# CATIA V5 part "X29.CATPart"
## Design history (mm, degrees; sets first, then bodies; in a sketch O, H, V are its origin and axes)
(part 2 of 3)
  St3DCurveFeature52 "CATSt3DCurveFeatureName": Order 6, CreationType 2, ClosureMode false, ConstructionPoints ({point type OnCurve, Support Join20, Real 0}; {point type OnCurve, Support St3DCurveFeature4, Real 0.751354}), SymmetryMode false
  Join21 "JOINJOINFRUIT": Elements (Join20; St3DCurveFeature52)
  Loft14 "OHTHEFRUIT": Sections (Join21; St3DCurveFeature50), Guides (St3DCurveFeature4; St3DCurveFeature51)
  Symmetry9: ToTransfor Loft14, Reference zx-plane
  Fill3: Boundary (St3DCurveFeature37; St3DCurveFeature36)
  Fill4: Boundary (edge of MultiSel6; edge of MultiSel6)
  Line9: type PtPt, FirstPoint vertex of St3DCurveFeature29, SecondPoint vertex of St3DCurveFeature31
  Point13: type OnCurve, Support Line9, Ratio 0.5
  Plane5: type OffsetPt, RefPlane xy-plane, RefPoint Point13
  Sketch12 on Plane5, origin (0, 0, 60.9519), H (1, 0, 0), V (0, 1, 0)
    line L1 (-1313.864, 33.3458) -> (-1313.864, 0)
    point P1 (-1313.864, 0)
    line L2 (-1313.864, 0) -> (-1285.9, 0)
    point P2 (-1285.9, 0)
    coincidence: P1 H
    vertical: L1 V
    horizontal: L2 H
  Line10: type PtPt, FirstPoint vertex [element of Sketch12 | element of Sketch12], SecondPoint vertex of St3DCurveFeature29
  Circle8: type 2PointsRad, Start 0, End 180, FirstPoint vertex of St3DCurveFeature29, SecondPoint vertex of St3DCurveFeature31, Support Sketch12.L2, Radius 62.383
  Plane6: type 3Points, Element1 vertex [element of Sketch12 | element of Sketch12], Element2 vertex of St3DCurveFeature29, Element3 vertex of St3DCurveFeature31
  Sketch13 on Plane6, origin (-1313.864, 0, 0), H (0, -1, 0), V (0, 0, 1)
    projected point E1 (0, 60.9519) from vertex [element of Sketch12 | element of Sketch12]
    arc A1 centre (0, 60.9519) radius 62.3831 from (-33.3458, 113.6748) to (-33.3458, 8.2289) ccw
  Loft15 "IMPROVED TURBINE INTAKE": Sections (St3DCurveFeature32; St3DCurveFeature34; Sketch13.A1), Guides (St3DCurveFeature29; St3DCurveFeature31)
  Symmetry10: ToTransfor Loft15, Reference zx-plane
  Sketch14 on Plane6, origin (-1313.864, 0, 0), H (0, -1, 0), V (0, 0, 1)
    projected point E1 (0, 60.9519) from vertex of Sketch13.E1
    projected point E2 (-33.3458, 113.6748) from vertex of St3DCurveFeature29
  Sketch15 on Plane5, origin (0, 0, 60.9519), H (1, 0, 0), V (0, 1, 0)
    projected line E1 (-1416.7, -3.85) -> (-1396.2, -3.85) from Sketch7.L16
    projected line E2 (-1396.2, -3.85) -> (-1396.2, 40.7) from Sketch7.L15
  Circle9: type CenterAxis, Start 0, End 180, Pt vertex of Sketch14.E2, Axis {line type PtPt, FirstPoint vertex of Sketch14.E1, SecondPoint Sketch12.P2}, Radius 62.383
  Point14: type OnPlane, Support zx-plane, RefPoint {extract ExtractElem vertex of St3DCurveFeature53}, H 0, V 0, Direction (-1, 0, 0)
  St3DCurveFeature53 "CATSt3DCurveFeatureName": Order 6, CreationType 2, ClosureMode false, ConstructionPoints ({point type OnCurve, Support Join18, Real 0.5}; {point type Coord, X -1064.6398, Y 0, Z 114.1394}; {point type Coord, X -1120.2775, Y 0, Z 116.1082}; {point type Coord, X -1193.3538, Y 0, Z 118.8994}; {point type Coord, X -1262.5354, Y 0, Z 123.2155}; {point type Coord, X 0, Y 0, Z 0, RefPoint {intersect ToIntersect1 zx-plane, ToIntersect2 Circle9}}), SymmetryMode false
  St3DCurveFeature54 "CATSt3DCurveFeatureName": Order 6, CreationType 2, ClosureMode false, ConstructionPoints ({point type OnCurve, Support St3DCurveFeature53, Real 0.219235}; {point type Coord, X -1060.5942, Y 8.1231, Z 113.32}; {point type Coord, X -1060.5905, Y 21.1239, Z 110.6941}; {point type OnCurve, Support St3DCurveFeature29, Real 0.688548}), SymmetryMode false
  St3DCurveFeature55 "CATSt3DCurveFeatureName": Order 6, CreationType 2, ClosureMode false, ConstructionPoints ({point type OnCurve, Support St3DCurveFeature53, Real 0.494443}; {point type Coord, X -1149.914, Y 5.9376, Z 116.5421}; {point type Coord, X -1149.8784, Y 21.8631, Z 111.8728}; {point type OnCurve, Support St3DCurveFeature29, Real 0.798273}), SymmetryMode false
  St3DCurveFeature56 "CATSt3DCurveFeatureName": Order 6, CreationType 2, ClosureMode false, ConstructionPoints ({point type OnCurve, Support St3DCurveFeature53, Real 0.810661}; {point type Coord, X -1252.4315, Y 8.3831, Z 122.1937}; {point type Coord, X -1252.4439, Y 20.5266, Z 119.6729}; {point type OnCurve, Support St3DCurveFeature29, Real 0.92444}), SymmetryMode false
  St3DCurveFeature57 "CATSt3DCurveFeatureName": Order 6, CreationType 2, ClosureMode false, ConstructionPoints ({point type OnCurve, Support St3DCurveFeature53, Real 0.933465}; {point type Coord, X -1292.2767, Y 7.7806, Z 123.3227}; {point type Coord, X -1292.2891, Y 21.9459, Z 120.0376}; {point type OnCurve, Support St3DCurveFeature29, Real 0.973447}), SymmetryMode false
  Circle10: type 2PointsRad, Start 0, End 180, FirstPoint Point14, SecondPoint vertex of Sketch14.E2, Support Plane6, Radius 62.383
  Join22: Elements (St3DCurveFeature41; St3DCurveFeature50)
  Loft16: Sections (Join22; St3DCurveFeature54; St3DCurveFeature55; St3DCurveFeature56; Circle10), Guides (St3DCurveFeature53; St3DCurveFeature29)
  Symmetry11: ToTransfor Loft16, Reference zx-plane
  Plane7: type Offset, RefPlane xy-plane, Offset 291
  St3DCurveFeature58 "CATSt3DCurveFeatureName": Order 6, CreationType 2, ClosureMode false, ConstructionPoints ({point type Coord, X -1192.6514, Y 0, Z 150.1595}; {point type Coord, X -1409.6244, Y 0, Z 149.4221}), SymmetryMode false
  St3DCurveFeature59 "CATSt3DCurveFeatureName": Order 6, CreationType 2, ClosureMode false, ConstructionPoints ({point type Coord, X -1384.0864, Y 0, Z 318.7844}; {point type Coord, X -1452.3877, Y 0, Z 318.7844}), SymmetryMode false
  Sketch16 "TUBE DIAMETERS" on zx-plane, origin (0, 0, 0), H (-1, 0, 0), V (0, 0, 1)
    line L1 (1114.5, 138) -> (1114.5, 132.9)
    point P2 (1114.5, 127.8)
    line L2 (1120.4, 139.4) -> (1120.4, 132.75)
    point P4 (1120.4, 126.1)
    line L3 (1190.3, 149.0859) -> (1190.3, 132.4751)
    point P6 (1190.3, 115.8643)
    line L4 (1250.3, 148.5) -> (1250.3, 131.55)
    point P8 (1250.3, 114.6)
    line L5 (1431.6, 115.2) -> (1251.2, 115.2)
    line L6 (1449.8, 148.5) -> (1449.8, 131.85)
    point P11 (1449.8, 115.2)
    line L7 (1449.8, 131.85) -> (1438.8, 131.85)
    point P14 (1438.8, 131.85)
    line L8 (1250.3, 131.55) -> (1242.1, 131.55)
    point P16 (1242.1, 131.55)
    line L9 (1190.3, 132.4751) -> (1202.4, 132.4751)
    point P18 (1202.4, 132.4751)
    line L10 (1120.4, 132.75) -> (1124.8, 132.75)
    point P20 (1124.8, 132.75)
    line L11 (1114.5, 132.9) -> (1106.3, 132.9)
    point P22 (1106.3, 132.9)
    vertical: L1 V, L2 V, L3 V, L4 V, L6 V
    horizontal: L5 H, L7 H, L8 H, L9 H, L10 H, L11 H
    coincidence: P11 L5
  Circle11 "TUBE CIRCLES": type CenterAxis, Start 0, End 180, Pt vertex [element of Sketch16 | element of Sketch16], Axis {line type PtPt, FirstPoint vertex [element of Sketch16 | element of Sketch16], SecondPoint Sketch16.P22}, Radius 5.1
  Circle12: type CenterAxis, Start 0, End 180, Pt vertex [element of Sketch16 | element of Sketch16], Axis {line type PtPt, FirstPoint vertex [element of Sketch16 | element of Sketch16], SecondPoint Sketch16.P20}, Radius 6.65
  Circle13: type CenterAxis, Start 0, End 180, Pt vertex [element of Sketch16 | element of Sketch16], Axis {line type PtPt, FirstPoint vertex [element of Sketch16 | element of Sketch16], SecondPoint Sketch16.P18}, Radius 16.611
  Circle14: type CenterAxis, Start 0, End 180, Pt vertex [element of Sketch16 | element of Sketch16], Axis {line type PtPt, FirstPoint Sketch16.P14, SecondPoint vertex [element of Sketch16 | element of Sketch16]}, Radius 16.65
  Circle15: type CenterAxis, Start 0, End 180, Pt vertex [element of Sketch16 | element of Sketch16], Axis {line type PtPt, FirstPoint Sketch16.P16, SecondPoint vertex [element of Sketch16 | element of Sketch16]}, Radius 16.95
  Loft17: Sections (Circle11; Circle12; Circle13; Circle15; Circle14)
  Fill5: Boundary Circle11
  StTopoTypeFeature1 "CATStTopoTypeFeatureName": Children 2
  Loft18 "TOP TUBE THING": Sections (edge of StTopoTypeFeature1; Circle12; Circle13; Circle15; Circle14)
  Fill6: Boundary (edge of StTopoTypeFeature1; edge of StTopoTypeFeature1; edge of StTopoTypeFeature1; edge of StTopoTypeFeature1; edge of StTopoTypeFeature1)
  Sketch17 on Plane7, origin (0, 0, 291), H (1, 0, 0), V (0, 1, 0)
    spline S1 through (-1201.8, 0) (-1242, 3.2) (-1296.9, 6.1) (-1357.7, 6.6) (-1408.8, 3.2) (-1422.3, 0)
    spline S2 through (-1375.2, 0) (-1387.4, 2.2) (-1424.6, 2.2) (-1434.7, 0)
    point P1 (-1201.8, 0)
    point P2 (-1422.3, 0)
    point P3 (-1375.2, 0)
    point P4 (-1434.7, 0)
    coincidence: P1 H, P2 H, P3 H, P4 H
  Project3: ToProject {extract ExtractElem Sketch17.S1}, Support Loft18, Direction (0, 0, 1)
  Plane8: type OffsetPt, RefPlane xy-plane, RefPoint vertex of St3DCurveFeature59
  Project4: ToProject {extract ExtractElem Sketch17.S2}, Support Plane8, Direction Plane8
  Line11: type PtPt, FirstPoint vertex of Project3, SecondPoint vertex of Project4
  Line12: type PtPt, FirstPoint vertex of Project3, SecondPoint vertex of Project4
  Loft19: Sections (Project3; Project4), Guides (Line12; Line11)
  Symmetry12: ToTransfor Loft19, Reference zx-plane
  Fill7: Boundary (edge of Symmetry12; Project4)
  Sketch18 on zx-plane, origin (0, 0, 0), H (-1, 0, 0), V (0, 0, 1)
    line L1 (1455.5, 84.131) -> (1455.5, 61.181)
    point P1 (1455.5, 84.131)
    point P2 (1455.5, 38.231)
    line L2 (1455.5, 61.181) -> (1469.3, 61.181)
    point P4 (1469.3, 61.181)
    vertical: L1 V
    horizontal: L2 H
  Circle16: type CenterAxis, Start 0, End 180, Pt vertex [element of Sketch18 | element of Sketch18], Axis {line type PtPt, FirstPoint vertex [element of Sketch18 | element of Sketch18], SecondPoint Sketch18.P4}, Radius 22.95
  Extremum1: Reference Circle16, Direction (1, 2, 3)
  Sketch19 on zx-plane, origin (0, 0, 0), H (-1, 0, 0), V (0, 0, 1)
    line L1 (1390.2, 104.4) -> (1390.2, 61.55)
    point P1 (1390.2, 104.4)
    point P2 (1390.2, 18.7)
    line L2 (1390.2, 61.55) -> (1369.7, 61.55)
    point P4 (1369.7, 61.55)
    vertical: L1 V
    horizontal: L2 H
  Circle17: type CenterAxis, Start 0, End 180, Pt vertex [element of Sketch19 | element of Sketch19], Axis {line type PtPt, FirstPoint vertex [element of Sketch19 | element of Sketch19], SecondPoint Sketch19.P4}, Radius 42.85
  Loft20: Sections (Circle9; Circle17; Circle16)
  Line13: type PtPt, FirstPoint Sketch18.P1, SecondPoint Sketch19.P1
  Line14: type PtPt, FirstPoint vertex [element of Sketch18 | element of Sketch18], SecondPoint vertex [element of Sketch19 | element of Sketch19]
  CircPattern1: of Line13, instances 24, angular step 15, axis from Line14
  Split5: ToCut Loft20, Cutting Circle17
  Fill8: Boundary edge of Loft18
  Fill9: Boundary Circle17
  Sketch20 on Plane7, origin (0, 0, 291), H (1, 0, 0), V (0, 1, 0)
    projected line E1 (-1390.2, 42.85) -> (-1390.2, -42.85) from Circle17
    projected line E2 (-1390.2, 4.1) -> (-1390.2, 0) from Circle17
    projected line E3 (-1455.5, -22.95) -> (-1455.5, 22.95) from Circle16
    projected line E4 (-1455.5, 0) -> (-1455.5, 4.1) from Circle16
    line L1 (-1455.5, 0) -> (-1390.2, 0)
    point P5 (-1455.5, 0)
    point P6 (-1390.2, 0)
    line L2 (-1455.5, 4.1) -> (-1390.2, 4.1)
    point P7 (-1455.5, 4.1)
    point P8 (-1390.2, 4.1)
    midpoint: P5 E3, P6 E1
    horizontal: L1 H, L2 H
    coincidence: P7 E3, P8 E1
  Project5: ToProject {extract ExtractElem Sketch20.L1}, Support {split ToCut Loft20, Cutting Circle17}, Direction (0, 0, 1)
  Project6: ToProject {extract ExtractElem Sketch20.L2}, Support {split ToCut Loft20, Cutting Circle17}, Direction (0, 0, 1)
  Project7: ToProject {extract ExtractElem Sketch20.E4}, Support {split ToCut Loft20, Cutting Circle17}, Direction (0, 0, 1)
  Project8: ToProject {extract ExtractElem Sketch20.E2}, Support {split ToCut Loft20, Cutting Circle17}, Direction (0, 0, 1)
  Join23: Elements (Project5; Project7; Project6; Project8)
  Join24 "9 S BOTTOM": Elements (St3DCurveFeature28; {symmetry ToTransfor St3DCurveFeature28, Reference zx-plane})
  Line15: type PtPt, FirstPoint vertex of Line7, SecondPoint vertex of St3DCurveFeature31
  StFrfSweepFeature4 "CATStFrfSweepFeatureName": Guide {extract ExtractElem edge of StFrfSweepFeature1}, Spine St3DCurveFeature31, SecondLimitPoint {point type OnCurve, Support St3DCurveFeature31, Real 1}, ProfileDeformation true, MaxOrderU 16, MaxOrderV 16, Profile Line15, FirstLimitPoint {point type OnCurve, Support St3DCurveFeature31, Real 0}, GuideSupport StFrfSweepFeature1
  Symmetry13: ToTransfor StFrfSweepFeature4, Reference zx-plane
  Line16: type PtDir, LineSecondUpto Loft15, RefPoint vertex [face of MultiSel5 | face of St3DCurveFeature28], Direction (0, 1, 0), Start 0, End 0
  St3DCurveFeature60 "LOWER INTAKE WING SECTION": Order 6, CreationType 2, ClosureMode false, ConstructionPoints ({point type OnCurve, Support Project2, Real 0}; {point type Coord, X -559.375, Y 62.4299, Z 3.5021}; {point type Coord, X -585.9734, Y 62.2412, Z -0.6915}; {point type Coord, X -638.5564, Y 61.7736, Z -8.6802}; {point type Coord, X -688.8547, Y 59.8651, Z -16.7888}; {point type Coord, X -741.086, Y 54.9491, Z -22.2141}; {point type OnCurve, Support Line16, Real 1}), SymmetryMode false
  Join25: Elements (St3DCurveFeature46; St3DCurveFeature48)
  Loft21: Sections (Join25; Line16), Guides St3DCurveFeature60
  Symmetry14: ToTransfor Loft21, Reference zx-plane
  St3DCurveFeature61 "A LITTLE HELP HERE PLEASE": Order 6, CreationType 2, ClosureMode false, ConstructionPoints ({point type Coord, X -508.205, Y 62.7154, Z -0.0049}; {point type Coord, X -512.2895, Y 62.5633, Z -0.0266}; {point type Coord, X -531.3045, Y 62.3962, Z 0.0637}; {point type Coord, X -559.375, Y 62.4299, Z -1.5121}; {point type Coord, X -585.9734, Y 62.2412, Z -3.635}; {point type Coord, X -638.5564, Y 61.7736, Z -8.6802}; {point type Coord, X -688.8547, Y 59.8651, Z -16.7888}; {point type Coord, X -741.086, Y 54.9491, Z -22.478}; {point type OnCurve, Support Line16, Real 1}; {point type Coord, X -831.316, Y 42.1554, Z -24.6143}; {point type Coord, X -856.3709, Y 39.0823, Z -25.0642}; {point type Coord, X -906.88, Y 33.4648, Z -24.5123}; {point type Coord, X -974.2931, Y 30.6249, Z -21.8907}; {point type Coord, X -1027.2833, Y 30.6513, Z -19.0312}; {point type Coord, X -1209.5607, Y 33.6414, Z -1.6668}; {point type Coord, X -1313.864, Y 33.3458, Z 8.2289}), SymmetryMode false
  St3DCurveFeature62 "SECONDARY KEEL": Order 6, CreationType 2, ClosureMode false, ConstructionPoints ({point type OnCurve, Support Line1, Real 0}; {point type Coord, X -8.1577, Y 0, Z -8.9268}; {point type Coord, X -16.8086, Y 0, Z -11.6761}; {point type Coord, X -32.7873, Y 0, Z -15.6372}; {point type Coord, X -54.4858, Y 0, Z -19.7845}; {point type Coord, X -80.8456, Y 0, Z -22.7321}; {point type Coord, X -117.4146, Y 0, Z -25.5885}; {point type Coord, X -152.4678, Y 0, Z -27.9816}; {point type Coord, X -207.8014, Y 0, Z -29.893}; {point type Coord, X -286.132, Y 0, Z -30.3156}; {point type Coord, X -356.7514, Y 0, Z -29.0986}; {point type Coord, X -430.7348, Y 0, Z -28.2478}; {point type Coord, X -530.0544, Y 0, Z -25.4118}; {point type Coord, X -600.3528, Y 0, Z -23.4266}; {point type Coord, X -625.014, Y 0, Z -23.143}; {point type Coord, X -675.559, Y 0, Z -23.143}; {point type Coord, X -730.5505, Y 0, Z -22.5758}; {point type Coord, X -809.2719, Y 0, Z -24.5014}; {point type OnCurve, Support Join24, Real 0.5}; {point type Coord, X -870.6227, Y 0, Z -24.5014}; {point type Coord, X -944.4781, Y 0, Z -24.5014}; {point type Coord, X -1018.3336, Y 0, Z -19.4189}; {point type Coord, X -1107.142, Y 0, Z -10.8177}; {point type Coord, X -1200.5359, Y 0, Z -5.9731}; {point type Coord, X 0, Y 0, Z 0, RefPoint Extract1}), SymmetryMode false
  Line17: type PtDir, LineSecondUpto Circle9, RefPoint {extract ExtractElem vertex of Sketch14.E1}, Direction (0, 0, 1), Start 0, End 0
  Intersect1: ToIntersect1 Circle9, ToIntersect2 zx-plane
  Extract1: ExtractElem vertex of Intersect1
  Circle18: type 2PointsRad, Start 0, End 180, FirstPoint vertex of Line9, SecondPoint Extract1, Support Plane6, Radius 62.383
  St3DCurveFeature63 "CATSt3DCurveFeatureName": Order 6, CreationType 2, ClosureMode false, ConstructionPoints ({point type OnCurve, Support St3DCurveFeature61, Real 0.478853}; {point type Coord, X -893.1664, Y 17.7325, Z -24.6272}; {point type OnCurve, Support St3DCurveFeature62, Real 0.679589}), SymmetryMode false
  St3DCurveFeature64 "CATSt3DCurveFeatureName": Order 6, CreationType 2, ClosureMode false, ConstructionPoints ({point type OnCurve, Support St3DCurveFeature61, Real 0.598015}; {point type Coord, X -989.509, Y 17.8413, Z -21.858}; {point type OnCurve, Support St3DCurveFeature62, Real 0.752872}), SymmetryMode false
  St3DCurveFeature65 "CATSt3DCurveFeatureName": Order 6, CreationType 2, ClosureMode false, ConstructionPoints ({point type OnCurve, Support St3DCurveFeature61, Real 0.685946}; {point type Coord, X -1060.6438, Y 14.1222, Z -15.1926}; {point type OnCurve, Support St3DCurveFeature62, Real 0.807238}), SymmetryMode false
  St3DCurveFeature66 "CATSt3DCurveFeatureName": Order 6, CreationType 2, ClosureMode false, ConstructionPoints ({point type OnCurve, Support St3DCurveFeature62, Real 0.95318}; {point type Coord, X -1252.3456, Y 15.9549, Z -3.0981}; {point type Coord, X -1252.3601, Y 24.9308, Z -1.1132}; {point type OnCurve, Support St3DCurveFeature61, Real 0.923801}), SymmetryMode false
  St3DCurveFeature67 "CATSt3DCurveFeatureName": Order 6, CreationType 2, ClosureMode false, ConstructionPoints ({point type OnCurve, Support St3DCurveFeature61, Real 0.973214}; {point type Coord, X -1292.2017, Y 22.4453, Z 0.7425}; {point type Coord, X -1292.1762, Y 8.2176, Z -2.1397}; {point type OnCurve, Support St3DCurveFeature62, Real 0.983482}), SymmetryMode false
  Loft22: Sections (Line16; St3DCurveFeature63; St3DCurveFeature64; St3DCurveFeature65; St3DCurveFeature66; St3DCurveFeature67; Circle18), Guides (St3DCurveFeature61; St3DCurveFeature62)
  Symmetry15: ToTransfor Loft22, Reference zx-plane
  St3DCurveFeature68 "WING ROOT TOP ENDGAME": Order 6, CreationType 2, ClosureMode false, ConstructionPoints ({point type Coord, X -819.6632, Y 79.273, Z 0}; {point type Coord, X -835.2322, Y 75.5015, Z 5.5279}; {point type Coord, X -855.5458, Y 72.1419, Z 12.6843}; {point type Coord, X -879.9246, Y 69.4113, Z 20.0948}; {point type Coord, X -898.5691, Y 67.7691, Z 23.8098}; {point type Coord, X -910.7505, Y 66.8316, Z 25.858}; {point type Coord, X -934.7742, Y 64.7318, Z 27.1425}; {point type Coord, X -976.7629, Y 62.2425, Z 28.3528}; {point type Coord, X -1015.0037, Y 61.0054, Z 28.886}; {point type Coord, X -1087.8837, Y 58.013, Z 31.7376}; {point type Coord, X -1130.8396, Y 55.9263, Z 32.9595}; {point type Coord, X -1250.2801, Y 51.565, Z 41.019}; {point type Coord, X -1387.319, Y 52.5398, Z 48.2581}), SymmetryMode false
  St3DCurveFeature69 "WING ROOT BOTT END GAME": Order 6, CreationType 2, ClosureMode false, ConstructionPoints ({point type Coord, X -819.6632, Y 79.273, Z 0}; {point type Coord, X -835.2322, Y 75.5015, Z -5.0214}; {point type Coord, X -855.5458, Y 72.1419, Z -5.4922}; {point type Coord, X -879.9246, Y 69.4113, Z -4.1128}; {point type Coord, X -898.5691, Y 67.7691, Z -2.868}; {point type Coord, X -910.7505, Y 66.8316, Z -1.7805}; {point type Coord, X -934.7742, Y 64.7318, Z 0.8708}; {point type Coord, X -976.7629, Y 62.2425, Z 4.7537}; {point type Coord, X -1015.0037, Y 61.0054, Z 8.2953}; {point type Coord, X -1087.8837, Y 58.013, Z 15.6027}; {point type Coord, X -1130.8396, Y 55.9263, Z 19.8774}; {point type Coord, X -1248.1339, Y 51.5973, Z 32.1446}; {point type OnCurve, Support St3DCurveFeature68, Real 1}), SymmetryMode false
  St3DCurveFeature70 "WING ROOT TOP ENDGAME DISPLACED": Order 6, CreationType 2, ClosureMode false, ConstructionPoints ({point type Coord, X -839.4938, Y 113.3905, Z 7.1018}; {point type Coord, X -848.149, Y 113.4163, Z 11.5253}; {point type Coord, X -855.5458, Y 113.3741, Z 14.4081}; {point type Coord, X -865.7559, Y 113.3543, Z 17.3583}; {point type Coord, X -879.9246, Y 113.409, Z 19.8987}; {point type Coord, X -884.1282, Y 113.4149, Z 20.482}; {point type Coord, X -898.5691, Y 113.3953, Z 21.5348}; {point type Coord, X -910.7505, Y 113.3877, Z 22.1268}; {point type Coord, X -934.7742, Y 113.4167, Z 23.4923}; {point type Coord, X -976.7629, Y 113.4195, Z 25.0461}; {point type Coord, X -1015.0037, Y 113.2635, Z 26.4654}; {point type Coord, X -1087.8837, Y 113.393, Z 29.3966}; {point type Coord, X -1130.8396, Y 113.3133, Z 30.6185}; {point type Coord, X -1250.2801, Y 113.1206, Z 37.6138}; {point type Coord, X -1387.319, Y 112.3064, Z 48.2581}), SymmetryMode false
  St3DCurveFeature71 "WING ROOT BOTT END GAME DISPLACED": Order 6, CreationType 2, ClosureMode false, ConstructionPoints ({point type OnCurve, Support St3DCurveFeature70, Real 0}; {point type Coord, X -848.4495, Y 113.3699, Z 3.7363}; {point type Coord, X -855.5458, Y 113.379, Z 2.5201}; {point type Coord, X -879.9246, Y 113.4049, Z 3.5269}; {point type Coord, X -898.5691, Y 113.4818, Z 4.8649}; {point type Coord, X -910.7505, Y 113.4065, Z 5.9524}; {point type Coord, X -934.7742, Y 113.3803, Z 8.4173}; {point type Coord, X -976.7629, Y 113.4699, Z 12.9084}; {point type Coord, X -1015.0037, Y 113.3702, Z 15.2806}; {point type Coord, X -1087.8837, Y 113.4106, Z 20.2825}; {point type Coord, X -1130.8396, Y 113.3957, Z 23.776}; {point type Coord, X -1248.1339, Y 113.1975, Z 33.3851}; {point type OnCurve, Support St3DCurveFeature70, Real 1}), SymmetryMode false
  Plane9: type OffsetPt, RefPlane zx-plane, RefPoint Sketch9.P3
  Intersect2: ToIntersect1 Loft9, ToIntersect2 Plane9
  Intersect3: ToIntersect1 Loft8, ToIntersect2 Plane9
  Fill10: Boundary (St3DCurveFeature70; St3DCurveFeature71)
  Line18: type PtPt, FirstPoint vertex of St3DCurveFeature68, SecondPoint vertex of St3DCurveFeature70
  Line19: type PtPt, FirstPoint vertex of St3DCurveFeature39, SecondPoint vertex of St3DCurveFeature70
  Loft23: Sections (St3DCurveFeature68; St3DCurveFeature70), Guides (Line19; Line18)
  Loft24: Sections (St3DCurveFeature69; St3DCurveFeature71), Guides Line18
  MultiSel8
  Intersect4: ToIntersect1 zx-plane, ToIntersect2 Loft3
  Intersect5: ToIntersect1 zx-plane, ToIntersect2 Loft4
  Sketch21 on Plane3, origin (0, 291, 0), H (-1, 0, 0), V (0, 0, 1)
    projected curve E1 from Intersect5
    line L1 (55, 22.7862) -> (55, -19.8628)
    point P4 (55, -19.8628)
    line L2 (175, 47.8726) -> (175, -29.0246)
    point P6 (175, -29.0246)
    line L3 (237.8, 59.8839) -> (237.8, -30.3061)
    point P8 (237.8, -30.3061)
    line L4 (292.3, 70.8406) -> (292.3, -30.2462)
    point P10 (292.3, -30.2462)
    line L5 (355.4, 92.0592) -> (355.4, -29.1201)
    point P12 (355.4, -29.1201)
    line L6 (393.5, 108.3367) -> (393.5, -28.6599)
    point P14 (393.5, -28.6599)
    line L7 (441.2, 122.6135) -> (441.2, -28.0744)
    point P16 (441.2, -28.0744)
    line L8 (476, 126.7101) -> (476, -27.2322)
    point P18 (476, -27.2322)
    line L9 (543.6, 126.5084) -> (543.6, -24.954)
    point P20 (543.6, -24.954)
    line L10 (600, 121.1313) -> (600, -23.4328)
    point P22 (600, -23.4328)
    line L11 (104.3, 33.9441) -> (104.3, -24.5762)
    point P24 (104.3, -24.5762)
    line L12 (143.4, 41.8115) -> (143.4, -27.4386)
    point P26 (143.4, -27.4386)
    coincidence: P4 E1, P6 E1, P8 E1, P10 E1, P12 E1, P14 E1, P16 E1, P18 E1, P20 E1, P22 E1, P24 E1, P26 E1
    vertical: L1 V, L2 V, L3 V, L4 V, L5 V, L6 V, L7 V, L8 V, L9 V, L10 V, L11 V, L12 V
  Project9: ToProject {multiextract ListOfMultiExtractConstraints (MultiExtractConstraint Sketch21.L1; MultiExtractConstraint Sketch21.L11; MultiExtractConstraint Sketch21.L12; MultiExtractConstraint Sketch21.L2; MultiExtractConstraint Sketch21.L3; MultiExtractConstraint Sketch21.L4; MultiExtractConstraint Sketch21.L5; MultiExtractConstraint Sketch21.L6; MultiExtractConstraint Sketch21.L7; MultiExtractConstraint Sketch21.L8; MultiExtractConstraint Sketch21.L9; MultiExtractConstraint Sketch21.L10)}, Support {multiextract ListOfMultiExtractConstraints (MultiExtractConstraint face of Loft3; MultiExtractConstraint face of Loft4)}, Direction (0, 1, 0)
  Blend1: StartLimit {blendlimit Curve Intersect4, Support Loft3}, EndLimit {blendlimit Curve Intersect5, Support Loft4}
  St3DCurveFeature72 "CATSt3DCurveFeatureName": Order 6, CreationType 2, ClosureMode false, ConstructionPoints ({point type OnCurve, Support Intersect4, Real 0.561099}; {point type Coord, X -355.4, Y 15.4213, Z 88.6211}; {point type Coord, X -355.4001, Y 28.162, Z 76.9846}; {point type Coord, X -355.4, Y 35.4381, Z 64.4308}; {point type Coord, X -355.4, Y 42.5313, Z 47.5628}; {point type Coord, X -355.4001, Y 46.7259, Z 32.527}; {point type Coord, X -355.4, Y 49.4201, Z 16.0901}; {point type Coord, X -355.4, Y 50.4958, Z 0}; {point type Coord, X -355.4, Y 48.0808, Z -15.3916}; {point type Coord, X -355.4, Y 35.4525, Z -26.09}; {point type Coord, X -355.4, Y 19.525, Z -28.4499}; {point type OnCurve, Support Intersect5, Real 0.565176}), SymmetryMode false
  Plane10: type Offset, RefPlane xy-plane, Offset 1
  Plane11: type Offset, RefPlane xy-plane, Offset 1, reversed
  Intersect6: ToIntersect1 Loft3, ToIntersect2 Plane10
  Extract2: ExtractElem edge of Intersect6
  Intersect7: ToIntersect1 Loft4, ToIntersect2 Plane11
  Extract3: ExtractElem edge of Intersect7
  Join26: Elements (Join2; Join10)
  Project10: ToProject St3DCurveFeature4, Support Loft3, Direction (0, 1, 0)
  Intersect8: ToIntersect1 zx-plane, ToIntersect2 Loft3
  Split6: ToCut Intersect8, Cutting vertex of St3DCurveFeature4
  St3DCurveFeature73 "CATSt3DCurveFeatureName": Order 6, CreationType 2, ClosureMode false, ConstructionPoints ({point type OnCurve, Support St3DCurveFeature5, Real 0.228358}; {point type Coord, X -314.3415, Y 1.8332, Z 75.4181}; {point type Coord, X -316.8842, Y 7.3821, Z 75.2006}; {point type Coord, X -319.6261, Y 11.0741, Z 74.9841}; {point type Coord, X -323.9821, Y 15.3852, Z 74.6245}; {point type Coord, X -327.4218, Y 18.0789, Z 74.3128}; {point type Coord, X -331.264, Y 20.7701, Z 73.9983}; {point type Coord, X -336.765, Y 24.0359, Z 73.5381}; {point type Coord, X -343.657, Y 27.3619, Z 72.9256}; {point type Coord, X -355.1724, Y 31.6887, Z 72.4729}; {point type Coord, X -370.8877, Y 36.3523, Z 72.1927}; {point type Coord, X -383.7912, Y 38.4954, Z 72.1897}; {point type Coord, X -397.3184, Y 39.8515, Z 72.0898}; {point type Coord, X -410.2175, Y 40.3042, Z 72.0663}; {point type Coord, X -425.4017, Y 40.2956, Z 71.9107}; {point type Coord, X -445.88, Y 40.0632, Z 72.8633}; {point type Coord, X -475.1823, Y 39.9786, Z 73.1473}; {point type Coord, X -502.6331, Y 40.1639, Z 74.0639}; {point type Coord, X -535.3124, Y 39.986, Z 75.7138}; {point type Coord, X -568.9066, Y 40.0706, Z 80.0391}; {point type Coord, X -609.7247, Y 39.4157, Z 85.4714}; {point type Coord, X -649.066, Y 38.9447, Z 89.9952}; {point type Coord, X -688.7982, Y 37.2164, Z 93.6057}; {point type Coord, X -718.2576, Y 35.6931, Z 96.5137}; {point type Coord, X -745.7382, Y 33.8178, Z 98.8225}; {point type Coord, X -777.5668, Y 30.4924, Z 101.3612}; {point type Coord, X -811.1523, Y 27.5214, Z 104.1194}; {point type Coord, X -849.8104, Y 23.8172, Z 106.5843}; {point type Coord, X -883.9333, Y 20.3055, Z 108.4864}; {point type Coord, X -923.3079, Y 16.9587, Z 111.2445}; {point type Coord, X -963.1815, Y 14.1496, Z 113.0833}; {point type Coord, X -989.4026, Y 11.559, Z 113.0833}), SymmetryMode false
  Split7: ToCut St3DCurveFeature73, Cutting vertex of Split3
  Symmetry16: ToTransfor Split7, Reference zx-plane
  Sketch22 on Plane3, origin (0, 291, 0), H (-1, 0, 0), V (0, 0, 1)
    projected curve E1 from edge of Symmetry16
  Project11: ToProject Sketch22, Support Loft3, Direction (0, 1, 0)
  Symmetry17: ToTransfor Project11, Reference zx-plane
  Line20: type PtPt, FirstPoint vertex of Symmetry17, SecondPoint vertex of Project11
  Project12: ToProject Line20, Support {multiextract ListOfMultiExtractConstraints (MultiExtractConstraint face of Loft3; MultiExtractConstraint face of Loft3)}, Direction (0, 0, 1)
  Split8: ToCut {multiextract ListOfMultiExtractConstraints (MultiExtractConstraint face of Loft3; MultiExtractConstraint face of Loft3)}, Cutting {multiextract ListOfMultiExtractConstraints (MultiExtractConstraint edge of Project11; MultiExtractConstraint edge of Project12; MultiExtractConstraint edge of Project12; MultiExtractConstraint edge of Symmetry17)}
  Join27: Elements (edge of Loft10; edge of Loft10)
  Join28 "5TH SECTION TOP": Elements (St3DCurveFeature16; {symmetry ToTransfor St3DCurveFeature16, Reference zx-plane})
  Join29 "6 SECTION TOP": Elements (St3DCurveFeature17; {symmetry ToTransfor St3DCurveFeature17, Reference zx-plane})
  Join30 "7 SECTION TOP": Elements (St3DCurveFeature18; {symmetry ToTransfor St3DCurveFeature18, Reference zx-plane})
  Join31 "8 SECTION TOP": Elements (St3DCurveFeature19; {symmetry ToTransfor St3DCurveFeature19, Reference zx-plane})
  Split9: ToCut Join28, Cutting Project11
  Split10: ToCut Split9, Cutting Symmetry17
  Split11: ToCut Join29, Cutting Project11
  Split12: ToCut Split11, Cutting Symmetry17
  Split13: ToCut Join30, Cutting Project11
  Split14: ToCut Split13, Cutting Symmetry17
  Split15: ToCut Join31, Cutting Project11
  Split16: ToCut Join8, Cutting Symmetry17
  Split17: ToCut Split16, Cutting Project11
  Loft25: Sections (Project12; Split10; Split12; Split14; Split17; Join27), Guides (Project11; Symmetry17)
  Sketch23 "COCKPIT SURFACE BREAKERS" on Plane7, origin (0, 0, 291), H (1, 0, 0), V (0, 1, 0)
    line L1 (-409.3442, 38.0221) -> (-409.3442, -38.0221)
    line L2 (-414.3, 38.4438) -> (-414.3, -38.4438)
    construction line L3 (-322.6, 0) -> (-322.6, -53.9)
    point P1 (-322.6, 0)
    spline S1 through (-409.3442, 38.0221) (-395.4959, 36.6678) (-370.3, 32.2) (-348.0038, 26.159) (-326.3035, 12.9489) (-322.6, 0)
    spline S2 through (-409.3442, -38.0221) (-395.4959, -36.6678) (-370.3, -32.2) (-348.0038, -26.159) (-326.3035, -12.9489) (-322.6, 0)
    line L4 (-414.3, 38.4438) -> (-514.2409, 38.4438)
    point P3 (-414.3, 38.4438)
    point P4 (-514.2409, 38.4438)
    construction line L5 (-525.8, 0) -> (-525.8, -25.526)
    point P5 (-525.8, 0)
    spline S3 through (-514.2409, 38.4438) (-520.623, 25.4047) (-524.6018, 12.1728) (-525.8, 0)
    spline S4 through (-531.6367, 38.4438) (-541.4882, 30.4068) (-551.2768, 12.1296) (-552.9, 0)
    construction line L6 (-552.9, 0) -> (-552.9, -23.1)
    point P7 (-552.9, 0)
    line L7 (-514.2409, 38.4438) -> (-531.6367, 38.4438)
    point P9 (-531.6367, 38.4438)
    point P10 (-514.2409, -38.4438)
    point P11 (-414.3, -38.4438)
    line L8 (-414.3, -38.4438) -> (-514.2409, -38.4438)
    point P12 (-531.6367, -38.4438)
    line L9 (-514.2409, -38.4438) -> (-531.6367, -38.4438)
    spline S5 through (-514.2409, -38.4438) (-520.623, -25.4047) (-524.6018, -12.1728) (-525.8, 0)
    spline S6 through (-531.6367, -38.4438) (-541.4882, -30.4068) (-551.2768, -12.1296) (-552.9, 0)
    construction line L10 (-575.8, 0) -> (-575.8, -26.3)
    point P13 (-575.8, 0)
    spline S7 through (-575.8, 0) (-573.8564, 13.9766) (-563.8, 32.4) (-543.4007, 42.3066)
    spline S8 through (-575.8, 0) (-573.8564, -13.9766) (-563.8, -32.4) (-543.4007, -42.3066)
    point P15 (-409.3442, -38.0221)
    point P16 (-409.3442, 38.0221)
    line L11 (-729.2, 81.1) -> (-729.2, -75.5)
    line L12 (-778.2, 13.9766) -> (-759.8, 13.9766)
    line L13 (-759.8, 13.9766) -> (-759.8, 5.1)
    line L14 (-759.8, 5.1) -> (-778.2, 5.1)
    line L15 (-778.2, 5.1) -> (-778.2, 13.9766)
    line L16 (-845.9, 17) -> (-819.8, 17)
    line L17 (-819.8, 17) -> (-819.8, 8.2)
    line L18 (-819.8, 8.2) -> (-845.9, 8.2)
    line L19 (-845.9, 8.2) -> (-845.9, 17)
    point P27 (-409.3442, 38.0221)
    point P28 (-322.6, 0)
    point P29 (-322.6, 0)
    point P30 (-409.3442, -38.0221)
    point P31 (-326.3035, 12.9489)
    point P32 (-326.3035, -12.9489)
    point P33 (-348.0038, 26.159)
    point P34 (-348.0038, -26.159)
    point P35 (-370.3, 32.2)
    point P36 (-370.3, -32.2)
    point P37 (-395.4959, 36.6678)
    point P38 (-395.4959, -36.6678)
    point P39 (-514.2409, 38.4438)
    point P40 (-525.8, 0)
    point P41 (-552.9, 0)
    point P42 (-531.6367, 38.4438)
    point P43 (-525.8, 0)
    point P44 (-514.2409, -38.4438)
    point P45 (-524.6018, 12.1728)
    point P46 (-524.6018, -12.1728)
    point P47 (-520.623, 25.4047)
    point P48 (-520.623, -25.4047)
    point P49 (-552.9, 0)
    point P50 (-531.6367, -38.4438)
    point P51 (-551.2768, 12.1296)
    point P52 (-551.2768, -12.1296)
    point P53 (-541.4882, 30.4068)
    point P54 (-541.4882, -30.4068)
    point P55 (-575.8, 0)
    point P56 (-543.4007, 42.3066)
    point P57 (-543.4007, -42.3066)
    point P58 (-575.8, 0)
    point P59 (-563.8, 32.4)
    point P60 (-563.8, -32.4)
    point P61 (-573.8564, 13.9766)
    point P62 (-573.8564, -13.9766)
    vertical: L1 V, L2 V, L3 V, L5 V, L6 V, L10 V, L11 V, L13 V, L15 V, L17 V, L19 V
    coincidence: P1 H, P27 L1, P28 P1, P5 H, P39 P4, P40 P5, P41 P7, P42 P9, P13 H, P55 P13, P30 P15, P27 P16, L4 L7, P7 H
    fix: L3, L5, L2, L6, L10, P9, P27, P49
    tangency: S1 L3, S3 L5, S4 L6, S7 L10
    symmetry: S1 S2 H, P28 P29 H, P27 P30 H, P31 P32 H, P33 P34 H, P35 P36 H, P37 P38 H, P4 P10 H, P3 P11 H, L4 L8 H, P9 P12 H, L7 L9 H, S3 S5 H, S4 S6 H, P40 P43 H, P39 P44 H, P45 P46 H, P47 P48 H, P41 P49 H, P42 P50 H, P51 P52 H, P53 P54 H, S7 S8 H, P56 P57 H, P55 P58 H, P59 P60 H, P61 P62 H
    horizontal: L4 H, L7 H, L12 H, L14 H, L16 H, L18 H
  Project13: ToProject {extract ExtractElem Sketch23.S7}, Support {multiextract ListOfMultiExtractConstraints MultiExtractConstraint face of Loft3}, Direction (0, 0, 1)
  Split18: ToCut {split ToCut {multiextract ListOfMultiExtractConstraints (MultiExtractConstraint face of Loft3; MultiExtractConstraint face of Loft3)}, Cutting {multiextract ListOfMultiExtractConstraints (MultiExtractConstraint edge of Project11; MultiExtractConstraint edge of Project12; MultiExtractConstraint edge of Project12; MultiExtractConstraint edge of Symmetry17)}}, Cutting Project13
  Project14: ToProject {extract ExtractElem Sketch23.L1}, Support {split ToCut {split ToCut {multiextract}, Cutting {multiextract}}, Cutting Project13}, Direction (0, 0, 1)
  Project15: ToProject {multiextract ListOfMultiExtractConstraints (MultiExtractConstraint Sketch23.L4; MultiExtractConstraint Sketch23.L2; MultiExtractConstraint Sketch23.L8; MultiExtractConstraint Sketch23.L9; MultiExtractConstraint Sketch23.S6; MultiExtractConstraint Sketch23.S4; MultiExtractConstraint Sketch23.L7)}, Support {split ToCut {split ToCut {multiextract}, Cutting {multiextract}}, Cutting Project13}, Direction (0, 0, 1)
  Extract4: ExtractElem Sketch23.S5
  Project16: ToProject {multiextract ListOfMultiExtractConstraints (MultiExtractConstraint Sketch23.S5; MultiExtractConstraint Sketch23.S3; MultiExtractConstraint Sketch23.L7; MultiExtractConstraint Sketch23.S4; MultiExtractConstraint Sketch23.S6; MultiExtractConstraint Sketch23.L9)}, Support {split ToCut {split ToCut {multiextract}, Cutting {multiextract}}, Cutting Project13}, Direction (0, 0, 1)
  Split19: ToCut {split ToCut {split ToCut {multiextract}, Cutting {multiextract}}, Cutting Project13}, Cutting Project15
  Split20: ToCut {split ToCut {split ToCut {split}, Cutting Project13}, Cutting Project15}, Cutting Project14
  Split21: ToCut Split19, Cutting Project16
  Point15: type OnCurve, Support Line7, Ratio 0.5
  Line21: type PtDir, RefPoint Point15, Direction (0, 1, 0), Start 0, End 18
  Plane12: type OffsetPt, RefPlane yz-plane, RefPoint vertex of St3DCurveFeature32
  Plane13: type Offset, RefPlane Plane12, Offset -2
  Sketch24 on Plane13, origin (-510.205, 0, 0), H (0, 1, 0), V (0, 0, 1)
    projected curve E1 from edge of St3DCurveFeature32
    projected line E2 (62.7154, 4.5947) -> (62.7154, -0.0049) from Line15
    projected line E3 (62.7154, 4.5947) -> (62.7154, 68.5947) from Line7
  Fill11: Boundary Sketch24
  Symmetry18: ToTransfor Fill11, Reference zx-plane
  St3DCurveFeature74 "CATSt3DCurveFeatureName": Order 6, CreationType 2, ClosureMode false, ConstructionPoints ({point type OnCurve, Support Join2, Real 0}; {point type Coord, X 49.3308, Y 3.5254, Z 0}; {point type Coord, X 151.1748, Y 0.9039, Z 0}; {point type Coord, X 274.2197, Y 0.174, Z 0}), SymmetryMode false
  Symmetry19: ToTransfor St3DCurveFeature74, Reference zx-plane
  Line22: type PtPt, FirstPoint vertex of Symmetry19, SecondPoint vertex of St3DCurveFeature74
  Point16: type OnCurve, Support Line22, Ratio 0.5
  Plane14: type OffsetPt, RefPlane yz-plane, RefPoint vertex of St3DCurveFeature74
  Circle19: type CtrPt, Start 0, End 180, Center Point16, Support Plane14, RefPoint vertex of St3DCurveFeature74
  Symmetry20: ToTransfor Circle19, Reference xy-plane
  Loft26: Sections (Join2; Circle19), Guides (St3DCurveFeature74; Symmetry19)
  Loft27: Sections (Join10; Symmetry20), Guides (St3DCurveFeature74; Symmetry19)
  Fill12: Boundary (Symmetry20; Circle19)
  Plane15: type Offset, RefPlane xy-plane, Offset 582
  Sketch25 "FRONT WING DECALS" on Plane15, origin (0, 0, 582), H (1, 0, 0), V (0, 1, 0)
    line L1 (-552.995, 109.1194) -> (-643.5106, 206.7552)
    point P1 (-552.995, 109.1194)
    line L2 (-643.5106, 206.7552) -> (-647.0106, 206.7552)
    line L3 (-647.0106, 206.7552) -> (-556.495, 109.1194)
    point P4 (-556.495, 109.1194)
    line L4 (-556.495, 109.1194) -> (-552.995, 109.1194)
    point P5 (-552.995, 109.1194)
    line L5 (-655.5106, 206.7552) -> (-564.995, 109.1194)
    point P6 (-564.995, 109.1194)
    line L6 (-564.995, 109.1194) -> (-579.995, 109.1194)
    point P8 (-579.995, 109.1194)
    line L7 (-579.995, 109.1194) -> (-670.5106, 206.7552)
    line L8 (-670.5106, 206.7552) -> (-655.5106, 206.7552)
    line L9 (-682.5106, 206.7552) -> (-679.0106, 206.7552)
    point P10 (-682.5106, 206.7552)
    line L10 (-679.0106, 206.7552) -> (-588.495, 109.1194)
    point P12 (-588.495, 109.1194)
    line L11 (-588.495, 109.1194) -> (-591.995, 109.1194)
    line L12 (-591.995, 109.1194) -> (-682.5106, 206.7552)
    reference projected line E1 (-642.6498, 208.7685) -> (-545.6321, 104.119) from edge of Loft2
    reference projected curve E2 from edge of Loft1
    reference projected curve E3 from edge of Loft1
    reference projected line E4 (-642.6498, 208.7685) -> (-545.6321, 104.119) from edge of Loft2
    length L2 = 3.5
    length L9 = 3.5 {= Sketch25.length(L2)}
    length L8 = 15
    distance L8 E2 = 2
    distance L4 E3 = 5
    distance P6 P4 = 8.5
    distance P12 P8 = 8.5 {= Sketch25.distance(P6 P4)}
    distance L1 E4 = 2
    distance L5 L7 = 11.0001 (reference)
    distance L7 L10 = 6.2334 (reference)
    distance L5 L7 = 11.0001 (reference)
    horizontal: L2 H, L4 H, L6 H, L8 H, L9 H, L11 H
    coincidence: P5 L1, P6 L4, P10 L8, P12 L4, L8 L2, L9 L8, P1 P5
    parallelism: L5 L1, L7 L3, L1 L3, L1 E1, L10 L12, L12 L7
  Project17: ToProject {extract ExtractElem Sketch25.L1}, Support Loft1, Direction (0, 0, 1)
  Project18: ToProject {extract ExtractElem Sketch25.L5}, Support Loft1, Direction (0, 0, 1)
  Project19: ToProject {extract ExtractElem Sketch25.L12}, Support Loft1, Direction (0, 0, 1)
  MultiSel9
  Split22: ToCut Loft1, Cutting Project17
  Split23: ToCut Split22, Cutting Project18
  Split24: ToCut Split23, Cutting Project19
  Split25: ToCut {symmetry ToTransfor Loft1, Reference zx-plane}, Cutting {symmetry ToTransfor Project17, Reference zx-plane}
  Split26: ToCut Split25, Cutting {symmetry ToTransfor Project18, Reference zx-plane}
  Split27: ToCut Split26, Cutting {symmetry ToTransfor Project19, Reference zx-plane}
  Sketch26 on Plane15, origin (0, 0, 582), H (1, 0, 0), V (0, 1, 0)
    line L1 (-813.83, 414.1151) -> (-1120.7127, 68.4341)
    point P1 (-813.83, 414.1151)
    reference projected line E1 (-728.3605, 414.245) -> (-846.518, 414.0654) from edge of Fill3
    projected line E2 (-846.518, 414.0654) -> (-1094.3073, 162.1678) from edge of Loft7
    projected line E3 (-867.4887, 161.7326) -> (-728.3605, 414.245) from edge of Loft7
    spline S1 through (-733.1237, 405.6) (-1074.2, 111.5) (-1310.6, 68.6)
    offsetcurve C1
    construction line L2 (-733.1237, 405.6) -> (-730.1668, 403.7273)
    point P9 (-733.1237, 405.6)
    construction line L3 through (-733.1237, 405.6) direction (0.5351, 0.8448)
    construction line L4 (-1310.6, 68.6) -> (-1310.5556, 65.1003)
    point P10 (-1310.6, 68.6)
    construction line L5 through (-1310.6, 68.6) direction (-0.9999, -0.0127)
    point P11 (-753.6057, 368.426)
    line L6 (-1310.6, 68.6) -> (-1310.5556, 65.1003)
    point P12 (-1310.6, 68.6)
    line L7 (-733.1237, 405.6) -> (-753.6057, 368.426)
    point P13 (-733.1237, 405.6)
    offsetcurve C2
    construction line L8 (-753.6057, 368.426) -> (-741.0098, 359.6555)
    construction line L9 through (-753.6057, 368.426) direction (0.5714, 0.8207)
    construction line L10 (-1310.5556, 65.1003) -> (-1310.4765, 58.8708)
    construction line L11 through (-1310.5556, 65.1003) direction (-0.9999, -0.0127)
    offsetcurve C3
    construction line L12 (-753.6057, 368.426) -> (-732.0053, 353.3857)
    construction line L13 through (-753.6057, 368.426) direction (0.5714, 0.8207)
    construction line L14 (-1310.5556, 65.1003) -> (-1310.3368, 47.8717)
    construction line L15 through (-1310.5556, 65.1003) direction (-0.9999, -0.0127)
    offsetcurve C4
    construction line L16 (-753.6057, 368.426) -> (-722.5672, 346.814)
    construction line L17 through (-753.6057, 368.426) direction (0.5714, 0.8207)
    construction line L18 (-1310.5556, 65.1003) -> (-1310.2578, 41.6422)
    construction line L19 through (-1310.5556, 65.1003) direction (-0.9999, -0.0127)
    offsetcurve C5
    construction line L20 (-753.6057, 368.426) -> (-717.3775, 343.2003)
    construction line L21 through (-753.6057, 368.426) direction (0.5714, 0.8207)
    construction line L22 (-1310.5556, 65.1003) -> (-1310.2133, 38.1425)
    construction line L23 through (-1310.5556, 65.1003) direction (-0.9999, -0.0127)
    point P22 (-776.6726, 326.5604)
    point P23 (-804.6019, 275.8698)
    point P24 (-817.1554, 253.0857)
    point P25 (-823.5743, 241.4355)
    point P26 (-733.1237, 405.6)
    point P27 (-1074.2, 111.5)
    point P28 (-1310.6, 68.6)
    coincidence: P1 E1, P26 E3, P26 P9, P28 P10, E3 P11, P28 P12, P26 P13, E3 P22, E3 P23, E3 P24, E3 P25
    fix: P1, P27, P26
    tangency: L3 S1, L5 S1, L9 C1, L11 C1, L13 C1, L15 C1, L17 C1, L19 C1, L21 C1, L23 C1
    perpendicularity: L2 L3, L4 L5, L8 L9, L10 L11, L12 L13, L14 L15, L16 L17, L18 L19, L20 L21, L22 L23
    parallelism: L7 E3
  Intersect9: ToIntersect1 Loft23, ToIntersect2 Loft15
  Sketch27 "REAR WING DECALS" on Plane15, origin (0, 0, 582), H (1, 0, 0), V (0, 1, 0)
    construction line L1 (-813.83, 414.1151) -> (-1120.7127, 68.4341)
    point P1 (-813.83, 414.1151)
    reference projected line E1 (-728.3605, 414.245) -> (-846.518, 414.0654) from edge of Fill3
    projected line E2 (-846.518, 414.0654) -> (-1094.3073, 162.1678) from edge of Loft7
    projected line E3 (-867.4887, 161.7326) -> (-728.3605, 414.245) from edge of Loft7
    spline S1 through (-733.1237, 405.6) (-1074.2, 111.5) (-1310.6, 68.6)
    offsetcurve C1
    construction line L2 (-733.1237, 405.6) -> (-730.1668, 403.7273)
    point P9 (-733.1237, 405.6)
    construction line L3 through (-733.1237, 405.6) direction (0.5351, 0.8448)
    construction line L4 (-1310.6, 68.6) -> (-1310.5556, 65.1003)
    point P10 (-1310.6, 68.6)
    construction line L5 through (-1310.6, 68.6) direction (-0.9999, -0.0127)
    point P11 (-753.6057, 368.426)
    line L6 (-1310.6, 68.6) -> (-1310.5556, 65.1003)
    point P12 (-1310.6, 68.6)
    line L7 (-733.1237, 405.6) -> (-753.6057, 368.426)
    point P13 (-733.1237, 405.6)
    offsetcurve C2
    construction line L8 (-753.6057, 368.426) -> (-741.0098, 359.6555)
    construction line L9 through (-753.6057, 368.426) direction (0.5714, 0.8207)
    construction line L10 (-1310.5556, 65.1003) -> (-1310.4765, 58.8708)
    construction line L11 through (-1310.5556, 65.1003) direction (-0.9999, -0.0127)
    offsetcurve C3
    construction line L12 (-753.6057, 368.426) -> (-732.0053, 353.3857)
    construction line L13 through (-753.6057, 368.426) direction (0.5714, 0.8207)
    construction line L14 (-1310.5556, 65.1003) -> (-1310.3368, 47.8717)
    construction line L15 through (-1310.5556, 65.1003) direction (-0.9999, -0.0127)
    offsetcurve C4
    construction line L16 (-753.6057, 368.426) -> (-722.5672, 346.814)
    construction line L17 through (-753.6057, 368.426) direction (0.5714, 0.8207)
    construction line L18 (-1310.5556, 65.1003) -> (-1310.2578, 41.6422)
    construction line L19 through (-1310.5556, 65.1003) direction (-0.9999, -0.0127)
    offsetcurve C5
    construction line L20 (-753.6057, 368.426) -> (-717.3775, 343.2003)
    construction line L21 through (-753.6057, 368.426) direction (0.5714, 0.8207)
    construction line L22 (-1310.5556, 65.1003) -> (-1310.2133, 38.1425)
    construction line L23 through (-1310.5556, 65.1003) direction (-0.9999, -0.0127)
    point P22 (-776.6726, 326.5604)
    point P23 (-804.6019, 275.8698)
    point P24 (-817.1554, 253.0857)
    point P25 (-823.5743, 241.4355)
    projected curve E4 from Intersect9
    projected curve E5 from Intersect9
    projected curve E6 from Intersect9
    point P38 (-1105.9853, 68.5117)
    point P39 (-1120.3149, 67.98)
    point P40 (-1149.4632, 66.9106)
    point P41 (-1228.7974, 64.1411)
    line L24 (-776.6726, 326.5604) -> (-804.6019, 275.8698)
    line L25 (-817.1554, 253.0857) -> (-823.5743, 241.4355)
    point P42 (-733.1237, 405.6)
    point P43 (-1074.2, 111.5)
    point P44 (-1310.6, 68.6)
    coincidence: P1 E1, P42 E3, P42 P9, P44 P10, E3 P11, P44 P12, P42 P13, E3 P22, E3 P23, E3 P24, E3 P25, E4 P38, E4 P39, E4 P40, E4 P41
    fix: P1, P43, P42
    tangency: L3 S1, L5 S1, L9 C1, L11 C1, L13 C1, L15 C1, L17 C1, L19 C1, L21 C1, L23 C1
    perpendicularity: L2 L3, L4 L5, L8 L9, L10 L11, L12 L13, L14 L15, L16 L17, L18 L19, L20 L21, L22 L23
    parallelism: L7 E3, L24 E3, L25 E3
  Project20: ToProject {extract ExtractElem Sketch27.S1}, Support {multiextract ListOfMultiExtractConstraints (MultiExtractConstraint face of Loft6; MultiExtractConstraint face of Loft23; MultiExtractConstraint face of Loft9)}, Direction (0, 0, 1)
  Project21: ToProject {extract ExtractElem Sketch27.S1}, Support {multiextract ListOfMultiExtractConstraints (MultiExtractConstraint face of Loft6; MultiExtractConstraint face of Loft9)}, Direction (0, 0, 1)
  Split28: ToCut Loft6, Cutting Project21
  Split29: ToCut Loft9, Cutting Project21
  Project22: ToProject {extract ExtractElem Sketch27.E6}, Support {multiextract ListOfMultiExtractConstraints (MultiExtractConstraint face of Loft6; MultiExtractConstraint face of Loft6; MultiExtractConstraint face of Loft9)}, Direction (0, 0, 1)
  Project23: ToProject {extract ExtractElem Sketch27.C4}, Support {multiextract ListOfMultiExtractConstraints (MultiExtractConstraint face of Loft6; MultiExtractConstraint face of Loft9)}, Direction (0, 0, 1)
  Project24: ToProject {extract ExtractElem Sketch27.C2}, Support Loft23, Direction (0, 0, 1)
  Project25: ToProject {extract ExtractElem Sketch27.C5}, Support Loft23, Direction (0, 0, 1)
  Split30: ToCut Split28, Cutting Project22
  Split31: ToCut Split30, Cutting Project23
  Split32: ToCut Split29, Cutting Project22
  Split33: ToCut Split32, Cutting Project23
  Split34: ToCut Loft23, Cutting Project20
  Split35: ToCut Split34, Cutting Project24
  Split36: ToCut Split35, Cutting Project25
  Join32: Elements (Split21; {split ToCut {split ToCut {split Cutting Project13}, Cutting Project15}, Cutting Project14})
  Join33: Elements Join32
  Sketch28 on Plane15, origin (0, 0, 582), H (1, 0, 0), V (0, 1, 0)
    projected curve E1 from Sketch23.S4
    projected curve E2 from Sketch23.S4
    projected curve E3 from Sketch23.S6
    projected curve E4 from Sketch23.S6
    projected curve E5 from Sketch23.S3
    projected curve E6 from Sketch23.S3
    projected curve E7 from Sketch23.S5
    projected curve E8 from Sketch23.S5
    offset curve E9 from edge of Split8
    offset curve E10 from edge of Split8
    offset curve E11 from edge of Split8
    point P9 (-316.5508, 1.9208)
    point P10 (-817.989, 24.3536)
    point P11 (-532.8882, 37.6855)
    point P12 (-532.8882, 37.6855)
    point P13 (-514.7835, 37.5058)
    point P14 (-817.989, -24.3536)
    point P15 (-316.5508, -1.9208)
    point P16 (-532.8882, -37.6855)
    construction frozenspline C1
    frozenspline C2
    line L1 (-414.0867, 37.9447) -> (-414.0867, -37.9447)
    point P17 (-414.0867, 37.9447)
    point P18 (-414.0867, -37.9447)
    point P19 (-532.8882, -37.6855)
    point P20 (-514.7835, -37.5058)
    frozenspline C3
    coincidence: E1 P11, E9 P12, E9 P13, P17 E9, P18 C1, C1 P19, C1 P20
    symmetry: P10 P14 H, P9 P15 H, P11 P16 H
    vertical: L1 V
  Project26: ToProject {multiextract ListOfMultiExtractConstraints (MultiExtractConstraint Sketch28.E11; MultiExtractConstraint Sketch28.E6; MultiExtractConstraint Sketch28.E8; MultiExtractConstraint Sketch28.C3; MultiExtractConstraint Sketch28.E4; MultiExtractConstraint Sketch28.E2)}, Support Join33, Direction (0, 0, 1)
  Project27: ToProject {multiextract ListOfMultiExtractConstraints (MultiExtractConstraint Sketch28.E11; MultiExtractConstraint Sketch28.L1; MultiExtractConstraint Sketch28.C2; MultiExtractConstraint Sketch28.E8; MultiExtractConstraint Sketch28.E6)}, Support Join33, Direction (0, 0, 1)
  Sketch29 on Plane15, origin (0, 0, 582), H (1, 0, 0), V (0, 1, 0)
